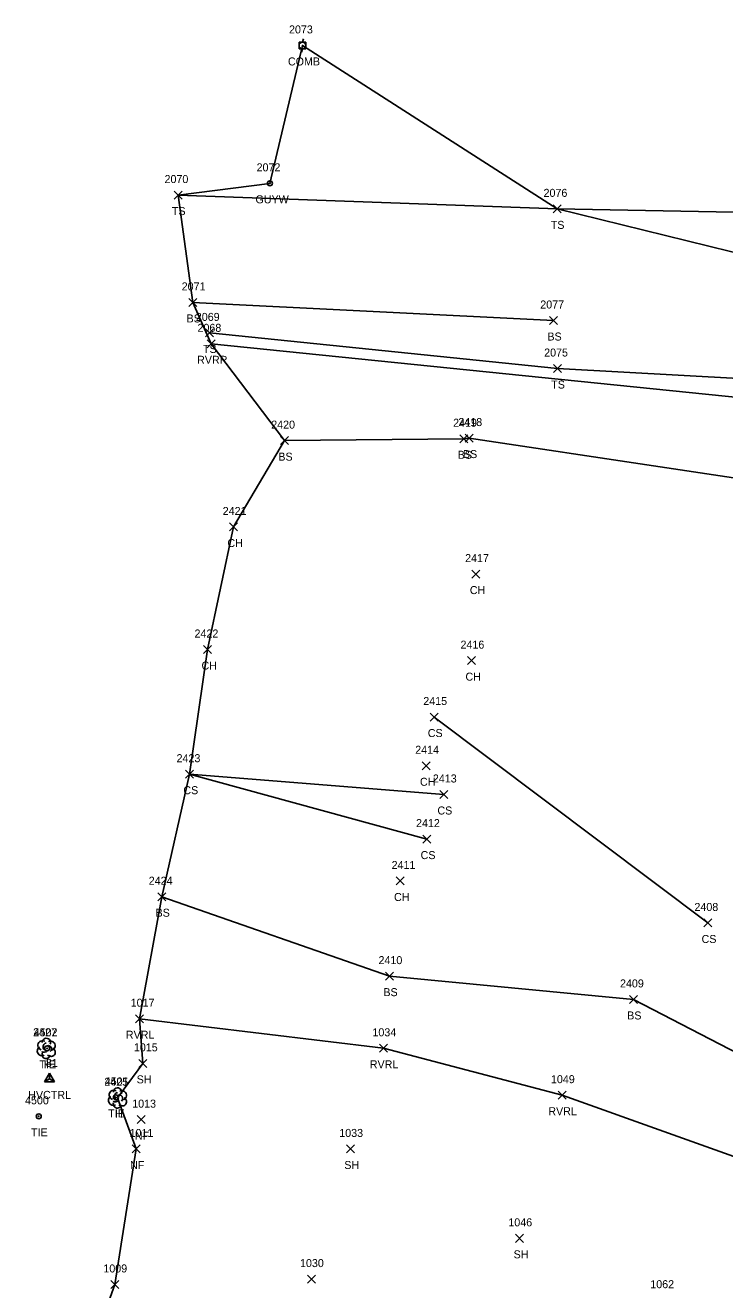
# Model space of a CAD drawing. Extents: x 1509053 to 1511576, y 400838 to 402572.
# Drawn here: x 1509077.3 to 1509252.1, y 402256.5 to 402572.4 of the extents above; entities that cross this region are included whole.
import ezdxf

# ---------------------------------------------------------------- set-up
doc = ezdxf.new("R2010")
doc.units = 0
for name, color, linetype in [('C_A', 7, 'Continuous'), ('C_I', 7, 'Continuous'), ('CBP', 7, 'Continuous'), ('CPSM', 7, 'Continuous'), ('L_A', 7, 'Continuous'), ('L_I', 7, 'Continuous'), ('L_TIC', 7, 'Continuous'), ('LAWE', 7, 'Continuous'), ('LELB', 7, 'Continuous'), ('LSOGP', 7, 'Continuous'), ('LTD', 7, 'Continuous'), ('U_A', 7, 'Continuous'), ('U_I', 7, 'Continuous'), ('UP', 7, 'Continuous'), ('UPGW', 7, 'Continuous')]:
    doc.layers.add(name, color=color, linetype=linetype)

msp = doc.modelspace()

# ---------------------------------------------------------------- linework, layer by layer
at = {"layer": 'CBP'}
for centre, radius in [((1509082.75, 402316.83), 0.625), ((1509082.75, 402316.83), 0.0833), ((1509099.94, 402304.58), 0.625), ((1509099.94, 402304.58), 0.0833), ((1509080.66, 402299.85), 0.625), ((1509080.66, 402299.85), 0.0833)]:
    msp.add_circle(centre, radius, dxfattribs=at)
at = {"layer": 'CPSM'}
for p, q in [((1509082.08, 402308.48), (1509083.33, 402310.64)), ((1509082.08, 402308.48), (1509083.33, 402309.2)), ((1509082.08, 402308.48), (1509084.58, 402308.48)), ((1509084.58, 402308.48), (1509083.33, 402310.64)), ((1509083.33, 402309.2), (1509083.33, 402310.64)), ((1509083.33, 402309.2), (1509083.33, 402309.2)), ((1509083.33, 402309.2), (1509084.58, 402308.48))]:
    msp.add_line(p, q, dxfattribs=at)
at = {"layer": 'L_TIC'}
for points in [[(1509114.54, 402529), (1509116.54, 402531)], [(1509116.54, 402529), (1509114.54, 402531)], [(1509209.26, 402525.55), (1509211.26, 402527.55)], [(1509211.26, 402525.55), (1509209.26, 402527.55)], [(1509118.17, 402502.18), (1509120.17, 402504.18)], [(1509120.17, 402502.18), (1509118.17, 402504.18)], [(1509208.38, 402497.67), (1509210.37, 402499.67)], [(1509210.37, 402497.67), (1509208.38, 402499.67)], [(1509122.32, 402494.56), (1509124.32, 402496.56)], [(1509124.32, 402494.56), (1509122.32, 402496.56)], [(1509122.74, 402491.84), (1509124.74, 402493.84)], [(1509124.74, 402491.84), (1509122.74, 402493.84)], [(1509209.35, 402485.66), (1509211.35, 402487.66)], [(1509211.35, 402485.66), (1509209.35, 402487.66)], [(1509141.12, 402467.65), (1509143.12, 402469.65)], [(1509143.12, 402467.65), (1509141.12, 402469.65)], [(1509185.96, 402468.12), (1509187.96, 402470.12)], [(1509187.96, 402468.12), (1509185.96, 402470.12)], [(1509187.27, 402468.29), (1509189.27, 402470.29)], [(1509189.27, 402468.29), (1509187.27, 402470.29)], [(1509128.34, 402446.08), (1509130.34, 402448.08)], [(1509130.34, 402446.08), (1509128.34, 402448.08)], [(1509188.94, 402434.31), (1509190.94, 402436.31)], [(1509190.94, 402434.31), (1509188.94, 402436.31)], [(1509121.87, 402415.47), (1509123.87, 402417.47)], [(1509123.87, 402415.47), (1509121.87, 402417.47)], [(1509187.85, 402412.69), (1509189.85, 402414.69)], [(1509189.85, 402412.69), (1509187.85, 402414.69)], [(1509178.48, 402398.6), (1509180.48, 402400.6)], [(1509180.48, 402398.6), (1509178.48, 402400.6)], [(1509176.48, 402386.43), (1509178.48, 402388.43)], [(1509178.48, 402386.43), (1509176.48, 402388.43)], [(1509117.38, 402384.32), (1509119.38, 402386.32)], [(1509119.38, 402384.32), (1509117.38, 402386.32)], [(1509117.38, 402384.32), (1509119.38, 402386.32)], [(1509119.38, 402384.32), (1509117.38, 402386.32)], [(1509180.89, 402379.25), (1509182.89, 402381.25)], [(1509182.89, 402379.25), (1509180.89, 402381.25)], [(1509176.68, 402368.11), (1509178.68, 402370.11)], [(1509178.68, 402368.11), (1509176.68, 402370.11)], [(1509169.99, 402357.64), (1509171.99, 402359.64)], [(1509171.99, 402357.64), (1509169.99, 402359.64)], [(1509110.41, 402353.71), (1509112.41, 402355.71)], [(1509112.41, 402353.71), (1509110.41, 402355.71)], [(1509246.92, 402347.15), (1509248.92, 402349.15)], [(1509248.92, 402347.15), (1509246.92, 402349.15)], [(1509167.37, 402333.87), (1509169.37, 402335.88)], [(1509169.37, 402333.87), (1509167.37, 402335.88)], [(1509228.32, 402328.05), (1509230.32, 402330.05)], [(1509230.32, 402328.05), (1509228.32, 402330.05)], [(1509104.87, 402323.24), (1509106.87, 402325.24)], [(1509106.87, 402323.24), (1509104.87, 402325.24)], [(1509165.85, 402315.84), (1509167.85, 402317.84)], [(1509167.85, 402315.84), (1509165.85, 402317.84)], [(1509105.65, 402312.07), (1509107.65, 402314.07)], [(1509107.65, 402312.07), (1509105.65, 402314.07)], [(1509210.49, 402304.13), (1509212.49, 402306.13)], [(1509212.49, 402304.13), (1509210.49, 402306.13)], [(1509105.23, 402298.02), (1509107.23, 402300.02)], [(1509107.23, 402298.02), (1509105.23, 402300.02)], [(1509104.01, 402290.69), (1509106.01, 402292.69)], [(1509106.01, 402290.69), (1509104.01, 402292.69)], [(1509157.56, 402290.7), (1509159.56, 402292.7)], [(1509159.56, 402290.7), (1509157.56, 402292.7)], [(1509199.88, 402268.37), (1509201.88, 402270.37)], [(1509201.88, 402268.37), (1509199.88, 402270.37)], [(1509098.68, 402256.85), (1509100.68, 402258.85)], [(1509100.68, 402256.85), (1509098.68, 402258.85)], [(1509147.83, 402258.19), (1509149.83, 402260.19)], [(1509149.83, 402258.19), (1509147.83, 402260.19)]]:
    msp.add_lwpolyline(points, dxfattribs=at)
at = {"layer": 'LAWE'}
for points in [[(1509123.74, 402492.84), (1509257.15, 402479.28), (1509295.46, 402474.2), (1509323.52, 402463.27), (1509340.74, 402459.51), (1509387.7, 402446.48), (1509437.74, 402415.48), (1509460.68, 402397.47), (1509520.56, 402367.88), (1509582.65, 402355.05), (1509635.23, 402334.07), (1509671.33, 402306.45), (1509693.48, 402289.28), (1509731.88, 402256.56), (1509764.07, 402209.44), (1509800.56, 402171.69), (1509807.78, 402147.71), (1509842.98, 402079.8), (1509863.82, 402015.71), (1509885.9, 401967.01)], [(1509105.87, 402324.24), (1509166.85, 402316.84), (1509211.49, 402305.13), (1509268.21, 402284.91), (1509312.96, 402259.07), (1509356.2, 402241.45), (1509401.11, 402232.66), (1509452.56, 402212.8), (1509514.16, 402192.04), (1509556.38, 402176.06), (1509631.87, 402126.97), (1509661.73, 402089.31), (1509701.86, 402034.14), (1509721.26, 402000.81), (1509742.13, 401921.74), (1509766.75, 401859.14), (1509782.51, 401819.75), (1509797.91, 401768.02), (1509814.1, 401723.17), (1509831.98, 401671.21)]]:
    msp.add_lwpolyline(points, dxfattribs=at)
at = {"layer": 'LELB'}
for points in [[(1509115.54, 402530), (1509210.25, 402526.55), (1509259.04, 402514.59), (1509304.29, 402509.73), (1509334.97, 402505.2), (1509343.55, 402508.97), (1509356.02, 402506.81), (1509405.08, 402490.51), (1509457.58, 402476.95), (1509474.2, 402464.72), (1509479.41, 402463.89), (1509501.59, 402438.85), (1509538.87, 402419.67), (1509601.4, 402398.68), (1509663.58, 402377.9), (1509703.97, 402366.5), (1509741.81, 402353.02), (1509786.94, 402318.01), (1509829.53, 402284.86)], [(1509119.17, 402503.18), (1509209.38, 402498.66)], [(1509123.32, 402495.56), (1509210.35, 402486.66), (1509257.12, 402484.12), (1509298.49, 402476.21), (1509320.42, 402465.74)], [(1510159.39, 401957.43), (1510109.97, 401933.78), (1510073.83, 401925.83), (1510030.04, 401920.72), (1509978.38, 401922.31), (1509938.9, 401925.26), (1509910.2, 401929.61), (1509860.63, 401969.45), (1509838.12, 402012.73), (1509801.23, 402094.39), (1509783.45, 402152.2), (1509742.56, 402227.61), (1509676.33, 402272.85), (1509632.84, 402314.37), (1509578.95, 402339.23), (1509514.2, 402355.92), (1509451.14, 402377.68), (1509400.45, 402407.85), (1509346.01, 402449.55), (1509331.23, 402458.28), (1509283.72, 402454.96), (1509188.27, 402469.29), (1509186.96, 402469.12), (1509142.12, 402468.65)], [(1509247.92, 402348.15), (1509179.48, 402399.6)], [(1509177.68, 402369.11), (1509118.38, 402385.32)], [(1509181.89, 402380.25), (1509118.38, 402385.32)], [(1509893.6, 401622.33), (1509860.64, 401660.7), (1509835.46, 401719.88), (1509820.45, 401775.67), (1509804.55, 401821.18), (1509793.58, 401877.47), (1509769.39, 401921.13), (1509750.31, 401995.31), (1509714.67, 402043.06), (1509675.87, 402101.28), (1509636.96, 402136.16), (1509603.47, 402183.37), (1509565.38, 402200.63), (1509506.19, 402219.72), (1509454.31, 402229.61), (1509409.3, 402242.42), (1509343.87, 402268.78), (1509286.85, 402299.31), (1509229.32, 402329.05), (1509168.38, 402334.88), (1509111.42, 402354.71)]]:
    msp.add_lwpolyline(points, dxfattribs=at)
at = {"layer": 'LSOGP'}
msp.add_lwpolyline([(1509459.59, 402484.75), (1509407.76, 402498.88), (1509356.02, 402506.81), (1509343.55, 402508.97), (1509333.66, 402515.1), (1509304.97, 402521.64), (1509263.28, 402525.53), (1509210.25, 402526.55), (1509146.57, 402567.38), (1509138.45, 402532.93), (1509115.54, 402530), (1509119.17, 402503.18), (1509123.74, 402492.84), (1509142.12, 402468.65), (1509129.34, 402447.08), (1509122.87, 402416.47), (1509118.38, 402385.32), (1509111.42, 402354.71), (1509105.87, 402324.24), (1509106.65, 402313.08), (1509100.33, 402304.48), (1509105.01, 402291.69), (1509099.68, 402257.85), (1509084.77, 402216.15)], dxfattribs=at)
at = {"layer": 'LTD'}
for p, q in [((1509082.52, 402316.86), (1509082.52, 402316.86)), ((1509082.52, 402316.86), (1509082.52, 402316.86)), ((1509100.33, 402304.48), (1509100.33, 402304.48)), ((1509100.33, 402304.48), (1509100.33, 402304.48))]:
    msp.add_line(p, q, dxfattribs=at)
for centre in [(1509082.57, 402318.29), (1509100.37, 402305.91)]:
    msp.add_arc(centre, 1.05, 335.5272, 180.9563, dxfattribs=at)
for centre, major_axis, ratio, start_param, end_param in [((1509081.73, 402317.53), (1.21, -0.51), 0.895232, 1.570796, 4.712389), ((1509082.31, 402317.32), (-0.208, -0.792), 0.645439, 3.141593, 6.283185), ((1509083.56, 402317.44), (-1.14, -0.48), 0.949671, 1.570796, 4.712389), ((1509081.44, 402316.15), (0.58, -1.04), 0.959034, 3.141593, 6.283185), ((1509082.52, 402315.36), (0.26, 1.06), 0.942809, 1.570796, 4.712389), ((1509082.06, 402316.11), (-0.625, -0.083), 0.423636, 0, 3.141593), ((1509083.02, 402316.69), (-0.5, 0.667), 0.989748, 3.141593, 6.283185), ((1509083.52, 402316.03), (-1.09, 0.79), 0.841452, 1.570796, 4.712389), ((1509099.54, 402305.15), (1.21, -0.51), 0.895232, 1.570796, 4.712389), ((1509100.12, 402304.94), (-0.208, -0.792), 0.645439, 3.141593, 6.283185), ((1509101.37, 402305.06), (-1.14, -0.48), 0.949671, 1.570796, 4.712389), ((1509099.24, 402303.77), (0.58, -1.04), 0.959034, 3.141593, 6.283185), ((1509100.33, 402302.98), (0.26, 1.06), 0.942809, 1.570796, 4.712389), ((1509099.87, 402303.73), (-0.625, -0.083), 0.423636, 0, 3.141593), ((1509100.83, 402304.31), (-0.5, 0.667), 0.989748, 3.141593, 6.283185), ((1509101.33, 402303.65), (-1.09, 0.79), 0.841452, 1.570796, 4.712389)]:
    msp.add_ellipse(centre, major_axis=major_axis, ratio=ratio, start_param=start_param, end_param=end_param, dxfattribs=at)
at = {"layer": 'UP'}
for p, q in [((1509145.74, 402566.55), (1509145.74, 402568.22)), ((1509145.74, 402568.22), (1509147.4, 402568.22)), ((1509146.82, 402569.05), (1509146.57, 402568.22)), ((1509147.4, 402568.22), (1509147.4, 402566.55)), ((1509147.4, 402566.55), (1509145.74, 402566.55)), ((1509146.32, 402565.72), (1509146.57, 402566.55)), ((1509146.57, 402567.38), (1509146.57, 402567.38))]:
    msp.add_line(p, q, dxfattribs=at)
msp.add_circle((1509146.57, 402567.38), 0.833, dxfattribs=at)
at = {"layer": 'UPGW'}
for radius in [0.625, 0.0833]:
    msp.add_circle((1509138.45, 402532.93), radius, dxfattribs=at)

# ---------------------------------------------------------------- texts
at = {"layer": 'C_A'}
for s, p in [('TIE', (1509080.83, 402311.83)), ('HVCTRL', (1509078.03, 402304.2)), ('TIE', (1509098.02, 402299.58)), ('TIE', (1509078.74, 402294.85))]:
    msp.add_text(s, height=2, dxfattribs=at).set_placement(p)
at = {"layer": 'C_I'}
for s, p in [('4502', (1509079.41, 402319.83)), ('81', (1509082.44, 402312.2)), ('4501', (1509097.17, 402307.58)), ('4500', (1509077.24, 402302.85))]:
    msp.add_text(s, height=2, dxfattribs=at).set_placement(p)
at = {"layer": 'L_A'}
for s, p in [('TS', (1509113.95, 402525)), ('TS', (1509208.66, 402521.55)), ('BS', (1509117.61, 402498.18)), ('BS', (1509207.82, 402493.66)), ('TS', (1509121.73, 402490.56)), ('RVRR', (1509120.25, 402487.84)), ('TS', (1509208.76, 402481.66)), ('BS', (1509140.56, 402463.65)), ('BS', (1509185.4, 402464.12)), ('BS', (1509186.71, 402464.29)), ('CH', (1509127.83, 402442.08)), ('CH', (1509188.43, 402430.31)), ('CH', (1509121.36, 402411.47)), ('CH', (1509187.34, 402408.69)), ('CS', (1509177.92, 402394.6)), ('CH', (1509175.96, 402382.43)), ('CS', (1509116.82, 402380.32)), ('CS', (1509116.82, 402380.32)), ('CS', (1509180.33, 402375.25)), ('CS', (1509176.12, 402364.11)), ('CH', (1509169.48, 402353.64)), ('BS', (1509109.86, 402349.71)), ('CS', (1509246.36, 402343.15)), ('BS', (1509166.82, 402329.87)), ('BS', (1509227.76, 402324.05)), ('RVRL', (1509102.44, 402319.24)), ('H', (1509081.95, 402311.86)), ('RVRL', (1509163.42, 402311.84)), ('SH', (1509105.14, 402308.08)), ('RVRL', (1509208.05, 402300.13)), ('H', (1509099.76, 402299.48)), ('NF', (1509104.71, 402294.02)), ('NF', (1509103.49, 402286.69)), ('SH', (1509157.05, 402286.7)), ('SH', (1509199.37, 402264.37))]:
    msp.add_text(s, height=2, dxfattribs=at).set_placement(p)
at = {"layer": 'L_I'}
for s, p in [('2070', (1509112.11, 402533)), ('2076', (1509206.86, 402529.55)), ('2071', (1509116.4, 402506.18)), ('2077', (1509206.04, 402501.66)), ('2069', (1509119.93, 402498.56)), ('2068', (1509120.35, 402495.84)), ('2075', (1509207.01, 402489.66)), ('2420', (1509138.78, 402471.65)), ('2419', (1509184.26, 402472.12)), ('2418', (1509185.57, 402472.29)), ('2421', (1509126.65, 402450.08)), ('2417', (1509187.25, 402438.31)), ('2422', (1509119.61, 402419.47)), ('2416', (1509186.1, 402416.69)), ('2415', (1509176.79, 402402.6)), ('2414', (1509174.78, 402390.43)), ('2423', (1509115.12, 402388.32)), ('2423', (1509115.12, 402388.32)), ('2413', (1509179.19, 402383.25)), ('2412', (1509174.98, 402372.11)), ('2411', (1509168.87, 402361.64)), ('2424', (1509108.16, 402357.71)), ('2408', (1509244.58, 402351.15)), ('2410', (1509165.6, 402337.87)), ('2409', (1509225.97, 402332.05)), ('1017', (1509103.66, 402327.24)), ('2427', (1509079.26, 402319.86)), ('1034', (1509164.08, 402319.84)), ('1015', (1509104.45, 402316.08)), ('2425', (1509097.07, 402307.48)), ('1049', (1509208.71, 402308.13)), ('1013', (1509104.03, 402302.02)), ('1011', (1509103.37, 402294.69)), ('1033', (1509155.79, 402294.7)), ('1046', (1509198.06, 402272.37)), ('1030', (1509145.98, 402262.19)), ('1009', (1509096.82, 402260.85)), ('1062', (1509233.54, 402256.91))]:
    msp.add_text(s, height=2, dxfattribs=at).set_placement(p)
at = {"layer": 'U_A'}
for s, p in [('COMB', (1509142.96, 402562.38)), ('GUYW', (1509134.85, 402527.93))]:
    msp.add_text(s, height=2, dxfattribs=at).set_placement(p)
at = {"layer": 'U_I'}
for s, p in [('2073', (1509143.23, 402570.38)), ('2072', (1509135.12, 402535.93))]:
    msp.add_text(s, height=2, dxfattribs=at).set_placement(p)

doc.saveas('drawing.dxf')
